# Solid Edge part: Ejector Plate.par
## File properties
Author: Dan
Template: metric part.par
Last saved by: Dan
Revision: 21
Application: Solid Edge
Density: 7833.000 kg/m^3
Accuracy: 0.990
Material: Steel
Face Style: Steel
Fill Style: ANSI32(Steel)
Virtual Style: Machined steel
Coef. of Thermal Exp: 1.3e-05
Thermal Conductivity: 32.0
Specific Heat: 481.0
Modulus of Elasticity: 199947953000.0
Poisson's Ratio: 0.29
Yield Stress: 262000766.0
Ultimate Stress: 358527364.0
Elongation: 0.0
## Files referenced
..\Wheel Mould.asm
C:\Drawing Files Other\Dave\Tente\HUP 125X36H45-TSA 02-07-2011\Wheel Mould\MH insert Outer.par
C:\Drawing Files Other\Dave\Tente\HUP 125X36H45-TSA 02-07-2011\Wheel Mould\Support Plate.par
ZC:\Drawing Files Other\Dave\Tente\HUP 125X36H45-TSA 02-07-2011\Wheel Mould\Wheel Mould.asm
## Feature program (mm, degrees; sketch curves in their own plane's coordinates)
sketch for "unnamed Protrusion 1" plane through (0, 0, 0) normal (0, 0, 1) x-axis (1, 0, 0)
extrude "unnamed Protrusion 1" add finite 16 along -normal
sketch for "Hole_9" plane through (0, 0, 0) normal (0, 0, 1) x-axis (1, 0, 0)
hole "Hole_9" diameter 8 through  VBottomAngle = 118 deg
sketch for "unnamed Hole 1" plane through (0, 0, 0) normal (0, 0, 1) x-axis (1, 0, 0)
  circle centre (0, 75) radius 36
hole "unnamed Hole 1" through
sketch for "unnamed Hole 2" plane through (0, 0, 0) normal (0, 0, 1) x-axis (1, 0, 0)
  hole centre (128, 180) bore radius 3.3235
hole "unnamed Hole 2" through
sketch for "unnamed Hole 3" plane through (0, 0, 0) normal (0, 0, 1) x-axis (1, 0, 0)
  hole centre (128, -180) bore radius 3.3235
hole "unnamed Hole 3" through
pattern "unnamed Pattern 1" of "Hole_9", "unnamed Hole 1", "unnamed Hole 2", "unnamed Hole 3"
sketch for "unnamed Cutout 1" #1 plane through (0, 0, 0) normal (0, 0, 1) x-axis (-1, 0, 0)
sketch for "unnamed Cutout 1" #2 plane through (0, 0, 0) normal (0, 0, 1) x-axis (-1, 0, 0)
  circle centre (0, -75) radius 36
extrude "unnamed Cutout 1" cut through along -normal
sketch for "Hole_13" plane through (0, 0, 0) normal (0, 0, 1) x-axis (1, 0, 0)
hole "Hole_13" diameter 10.5 through  CounterBoreDepth = 5.05 mm; VBottomAngle = 118 deg
sketch for "unnamed Hole 4" plane through (0, 0, 0) normal (0, 0, 1) x-axis (1, 0, 0)
hole "unnamed Hole 4" through
sketch for "unnamed Hole 5" plane through (0, 0, 0) normal (0, 0, 1) x-axis (1, 0, 0)
  hole centre (75, 170) bore radius 5.25
hole "unnamed Hole 5" through
sketch for "unnamed Hole 6" plane through (0, 0, 0) normal (0, 0, 1) x-axis (1, 0, 0)
  hole centre (75, -170) bore radius 5.25
hole "unnamed Hole 6" through
pattern "unnamed Pattern 2" of "Hole_13", "unnamed Hole 4", "unnamed Hole 5", "unnamed Hole 6"
sketch for "Hole_17" plane through (0, 0, 0) normal (0, 0, 1) x-axis (1, 0, 0)
  hole centre (-75, 75) bore radius 20
hole "Hole_17" diameter 40 through  CounterBoreDepth = 5.05 mm; VBottomAngle = 118 deg
sketch for "unnamed Hole 7" plane through (0, 0, 0) normal (0, 0, 1) x-axis (1, 0, 0)
  hole centre (75, 75) bore radius 20
hole "unnamed Hole 7" through
sketch for "unnamed Hole 8" plane through (0, 0, 0) normal (0, 0, 1) x-axis (1, 0, 0)
  hole centre (75, -75) bore radius 20
hole "unnamed Hole 8" through
sketch for "unnamed Hole 9" plane through (0, 0, 0) normal (0, 0, 1) x-axis (1, 0, 0)
  hole centre (-75, -75) bore radius 20
hole "unnamed Hole 9" through
pattern "unnamed Pattern 3" of "Hole_17", "unnamed Hole 7", "unnamed Hole 8", "unnamed Hole 9"
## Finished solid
Body 1: solid body, 36 faces, 56 edges, 8 vertices.
  Faces by surface: cylinder 22, plane 14
  Edges by curve: circle 44, line 12
Bounding box of the edges (mm): 280.000 x 396.000 x 16.000, from (-140, -198, -16) to (140, 198, 0).
Cylindrical faces by radius (mm): R3.3235 x4, R5.25 x4, R8.5 x4, R20 x4, R23 x4, R36 x2
Planar faces by outward normal: +x 1, +y 1, +z 9, -x 1, -y 1, -z 1
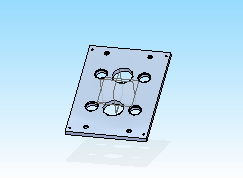
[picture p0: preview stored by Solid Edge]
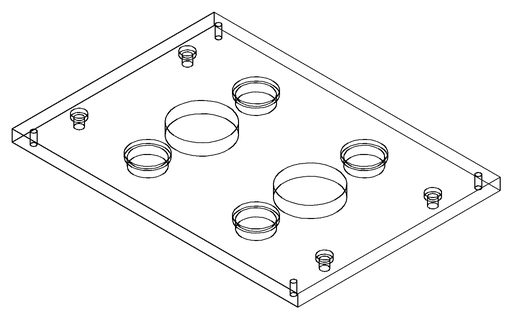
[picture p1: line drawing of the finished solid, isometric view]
